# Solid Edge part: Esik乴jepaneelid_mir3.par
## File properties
Author: Türk
Template: Iso Part.par
Last saved by: Türk
Revision: 4
Application: Solid Edge
Accuracy: 0,990
Username: Türk
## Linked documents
ljepaneelid.par
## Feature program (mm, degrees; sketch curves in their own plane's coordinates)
part copy "CopiedPart_1"
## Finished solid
Body 1: solid body, 141 faces, 376 edges, 233 vertices.
  Faces by surface: blend 40, plane 37, spline 22, cylinder 18, swept 13, offset 9, cone 1, sphere 1
  Edges by curve: intersection 169, line 92, circle 49, curve on surface 43, spline 20, ellipse 3
Bounding box of the edges (mm; curved faces can reach further): 930.951 x 1810.174 x 663.165, from (-930.9424, -960.1735, -191.0391) to (0.0086, 850, 472.1255).
Cylindrical faces by radius (mm): R6.5 x2, R20 x1, R46.25 x1, R56.25 x1, R60 x1, R70 x1, R90 x3, R100 x1, R101 x3, R303.2534 x1, R325 x1, R350 x2
Conical faces (half-angle, radius in mm at the cone's reference point): 15 deg R100 x1
Spherical faces by radius (mm): R45 x1
Planar faces by outward normal: +x 6, +y 4, +z 3, -x 2, -y 5, -z 5, oblique 12
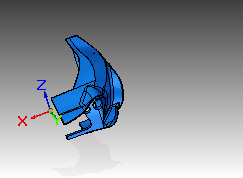
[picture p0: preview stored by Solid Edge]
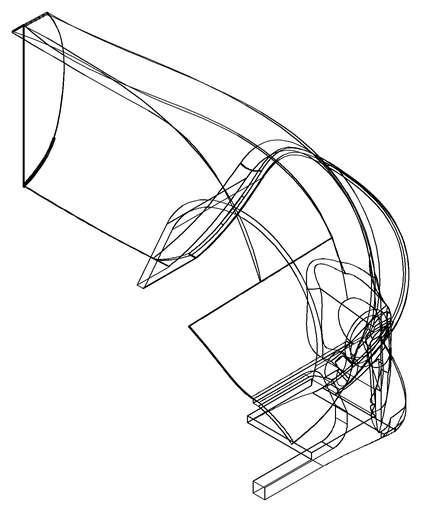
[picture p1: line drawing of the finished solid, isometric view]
